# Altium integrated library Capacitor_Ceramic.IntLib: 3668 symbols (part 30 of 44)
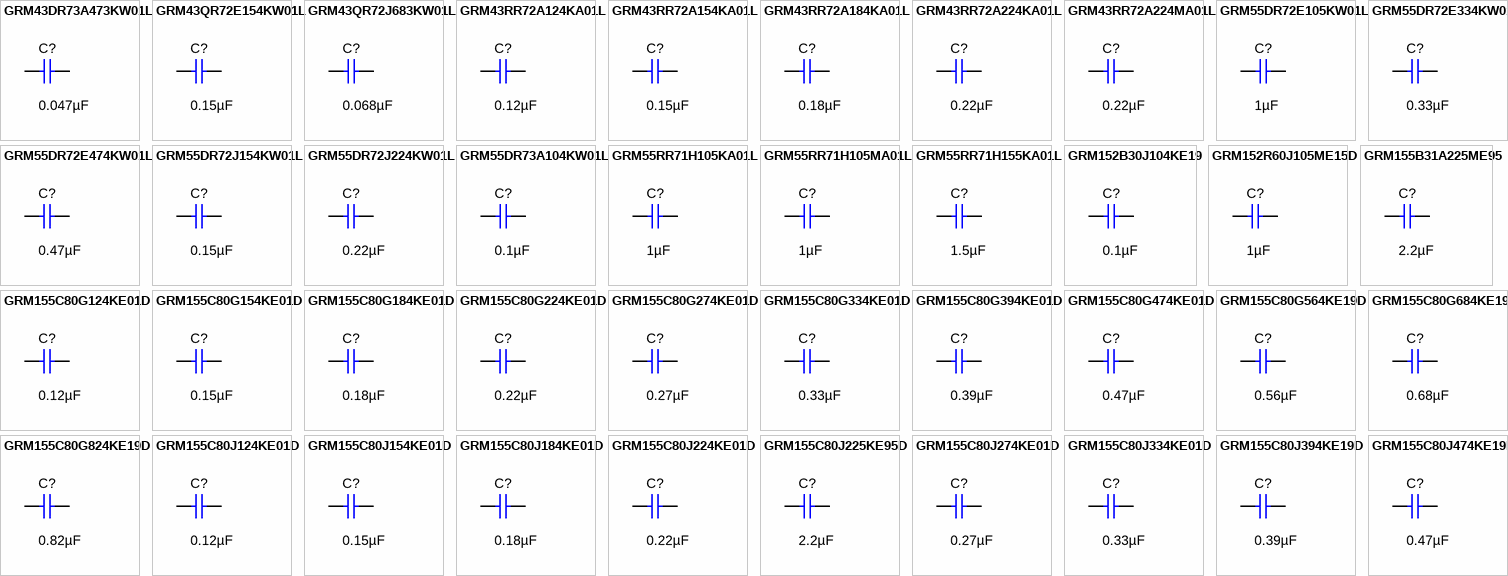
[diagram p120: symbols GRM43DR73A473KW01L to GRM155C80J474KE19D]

## GRM152R60J105ME15D
designator C?  ValueDisplayed: 1µF  (hidden comment: GRM152R60J105ME15D)
CAP, CERM, 1 µF, 6.3 V,+/- 20%, X5R, 0402; Manufacturer: MuRata; Polarized: N; CompType: Capacitor; Value: 1uF; U/M: EA; Cap_F: 0.000001; Tolerance_%: 20; VDC_V: 6.3; Value2: 6.3V; TaMin_C: -55; TaMax_C: 85; Cap_Case: 0402; SizeArea_mm2: 0.5; SizeAreaWB_mm2: 3; SizeX_mm: 1; SizeZ_mm: 0.6; AEC Category: Q200; Green_Lifecycle: Active; Green_REACh: Passed
signal-integrity model Cap
simulation model Cap
footprint 0402
footprint 0402M
footprint 0402L
footprint 0402S
pins: 1, 2

## GRM155B31A225ME95
designator C?  ValueDisplayed: 2.2µF  (hidden comment: GRM155B31A225ME95)
CAP, CERM, 2.2 µF, 10 V,+/- 20%, B, 0402; Manufacturer: MuRata; Polarized: N; CompType: Capacitor; Value: 2.2uF; U/M: EA; Cap_F: 0.0000022; Tolerance_%: 20; VDC_V: 10; Value2: 10V; TaMin_C: -25; TaMax_C: 85; Cap_Case: 0402; SizeArea_mm2: 0.5; SizeAreaWB_mm2: 3; SizeX_mm: 1; SizeZ_mm: 0.6; AEC Category: Q200
signal-integrity model Cap
simulation model Cap
footprint 0402
footprint 0402M
footprint 0402L
footprint 0402S
pins: 1, 2

## GRM155C80G124KE01D
designator C?  ValueDisplayed: 0.12µF  (hidden comment: GRM155C80G124KE01D)
CAP, CERM, 0.12 µF, 4 V,+/- 10%, X6S, 0402; Manufacturer: MuRata; Polarized: N; CompType: Capacitor; Value: 0.12uF; U/M: EA; Cap_F: 0.00000012; Tolerance_%: 10; VDC_V: 4; Value2: 4V; TaMin_C: -55; TaMax_C: 105; Cap_Case: 0402; SizeArea_mm2: 0.5; SizeAreaWB_mm2: 3; SizeX_mm: 1; SizeZ_mm: 0.6; AEC Category: Q200
signal-integrity model Cap
simulation model Cap
footprint 0402
footprint 0402M
footprint 0402L
footprint 0402S
pins: 1, 2

## GRM155C80G154KE01D
designator C?  ValueDisplayed: 0.15µF  (hidden comment: GRM155C80G154KE01D)
CAP, CERM, 0.15 µF, 4 V,+/- 10%, X6S, 0402; Manufacturer: MuRata; Polarized: N; CompType: Capacitor; Value: 0.15uF; U/M: EA; Cap_F: 0.00000015; Tolerance_%: 10; VDC_V: 4; Value2: 4V; TaMin_C: -55; TaMax_C: 105; Cap_Case: 0402; SizeArea_mm2: 0.5; SizeAreaWB_mm2: 3; SizeX_mm: 1; SizeZ_mm: 0.6; AEC Category: Q200
signal-integrity model Cap
simulation model Cap
footprint 0402
footprint 0402M
footprint 0402L
footprint 0402S
pins: 1, 2

## GRM155C80G184KE01D
designator C?  ValueDisplayed: 0.18µF  (hidden comment: GRM155C80G184KE01D)
CAP, CERM, 0.18 µF, 4 V,+/- 10%, X6S, 0402; Manufacturer: MuRata; Polarized: N; CompType: Capacitor; Value: 0.18uF; U/M: EA; Cap_F: 0.00000018; Tolerance_%: 10; VDC_V: 4; Value2: 4V; TaMin_C: -55; TaMax_C: 105; Cap_Case: 0402; SizeArea_mm2: 0.5; SizeAreaWB_mm2: 3; SizeX_mm: 1; SizeZ_mm: 0.6; AEC Category: Q200
signal-integrity model Cap
simulation model Cap
footprint 0402
footprint 0402M
footprint 0402L
footprint 0402S
pins: 1, 2

## GRM155C80G224KE01D
designator C?  ValueDisplayed: 0.22µF  (hidden comment: GRM155C80G224KE01D)
CAP, CERM, 0.22 µF, 4 V,+/- 10%, X6S, 0402; Manufacturer: MuRata; Polarized: N; CompType: Capacitor; Value: 0.22uF; U/M: EA; Cap_F: 0.00000022; Tolerance_%: 10; VDC_V: 4; Value2: 4V; TaMin_C: -55; TaMax_C: 105; Cap_Case: 0402; SizeArea_mm2: 0.5; SizeAreaWB_mm2: 3; SizeX_mm: 1; SizeZ_mm: 0.6; AEC Category: Q200
signal-integrity model Cap
simulation model Cap
footprint 0402
footprint 0402M
footprint 0402L
footprint 0402S
pins: 1, 2

## GRM155C80G274KE01D
designator C?  ValueDisplayed: 0.27µF  (hidden comment: GRM155C80G274KE01D)
CAP, CERM, 0.27 µF, 4 V,+/- 10%, X6S, 0402; Manufacturer: MuRata; Polarized: N; CompType: Capacitor; Value: 0.27uF; U/M: EA; Cap_F: 0.00000027; Tolerance_%: 10; VDC_V: 4; Value2: 4V; TaMin_C: -55; TaMax_C: 105; Cap_Case: 0402; SizeArea_mm2: 0.5; SizeAreaWB_mm2: 3; SizeX_mm: 1; SizeZ_mm: 0.6; AEC Category: Q200
signal-integrity model Cap
simulation model Cap
footprint 0402
footprint 0402M
footprint 0402L
footprint 0402S
pins: 1, 2

## GRM155C80G334KE01D
designator C?  ValueDisplayed: 0.33µF  (hidden comment: GRM155C80G334KE01D)
CAP, CERM, 0.33 µF, 4 V,+/- 10%, X6S, 0402; Manufacturer: MuRata; Polarized: N; CompType: Capacitor; Value: 0.33uF; U/M: EA; Cap_F: 0.00000033; Tolerance_%: 10; VDC_V: 4; Value2: 4V; TaMin_C: -55; TaMax_C: 105; Cap_Case: 0402; SizeArea_mm2: 0.5; SizeAreaWB_mm2: 3; SizeX_mm: 1; SizeZ_mm: 0.6; AEC Category: Q200
signal-integrity model Cap
simulation model Cap
footprint 0402
footprint 0402M
footprint 0402L
footprint 0402S
pins: 1, 2

## GRM155C80G394KE01D
designator C?  ValueDisplayed: 0.39µF  (hidden comment: GRM155C80G394KE01D)
CAP, CERM, 0.39 µF, 4 V,+/- 10%, X6S, 0402; Manufacturer: MuRata; Polarized: N; CompType: Capacitor; Value: 0.39uF; U/M: EA; Cap_F: 0.00000039; Tolerance_%: 10; VDC_V: 4; Value2: 4V; TaMin_C: -55; TaMax_C: 105; Cap_Case: 0402; SizeArea_mm2: 0.5; SizeAreaWB_mm2: 3; SizeX_mm: 1; SizeZ_mm: 0.6; AEC Category: Q200
signal-integrity model Cap
simulation model Cap
footprint 0402
footprint 0402M
footprint 0402L
footprint 0402S
pins: 1, 2

## GRM155C80G474KE01D
designator C?  ValueDisplayed: 0.47µF  (hidden comment: GRM155C80G474KE01D)
CAP, CERM, 0.47 µF, 4 V,+/- 10%, X6S, 0402; Manufacturer: MuRata; Polarized: N; CompType: Capacitor; Value: 0.47uF; U/M: EA; Cap_F: 0.00000047; Tolerance_%: 10; VDC_V: 4; Value2: 4V; TaMin_C: -55; TaMax_C: 105; Cap_Case: 0402; SizeArea_mm2: 0.5; SizeAreaWB_mm2: 3; SizeX_mm: 1; SizeZ_mm: 0.6; AEC Category: Q200
signal-integrity model Cap
simulation model Cap
footprint 0402
footprint 0402M
footprint 0402L
footprint 0402S
pins: 1, 2

## GRM155C80G564KE19D
designator C?  ValueDisplayed: 0.56µF  (hidden comment: GRM155C80G564KE19D)
CAP, CERM, 0.56 µF, 4 V,+/- 10%, X6S, 0402; Manufacturer: MuRata; Polarized: N; CompType: Capacitor; Value: 0.56uF; U/M: EA; Cap_F: 0.00000056; Tolerance_%: 10; VDC_V: 4; Value2: 4V; TaMin_C: -55; TaMax_C: 105; Cap_Case: 0402; SizeArea_mm2: 0.5; SizeAreaWB_mm2: 3; SizeX_mm: 1; SizeZ_mm: 0.6; AEC Category: Q200
signal-integrity model Cap
simulation model Cap
footprint 0402
footprint 0402M
footprint 0402L
footprint 0402S
pins: 1, 2

## GRM155C80G684KE19D
designator C?  ValueDisplayed: 0.68µF  (hidden comment: GRM155C80G684KE19D)
CAP, CERM, 0.68 µF, 4 V,+/- 10%, X6S, 0402; Manufacturer: MuRata; Polarized: N; CompType: Capacitor; Value: 0.68uF; U/M: EA; Cap_F: 0.00000068; Tolerance_%: 10; VDC_V: 4; Value2: 4V; TaMin_C: -55; TaMax_C: 105; Cap_Case: 0402; SizeArea_mm2: 0.5; SizeAreaWB_mm2: 3; SizeX_mm: 1; SizeZ_mm: 0.6; AEC Category: Q200
signal-integrity model Cap
simulation model Cap
footprint 0402
footprint 0402M
footprint 0402L
footprint 0402S
pins: 1, 2

## GRM155C80G824KE19D
designator C?  ValueDisplayed: 0.82µF  (hidden comment: GRM155C80G824KE19D)
CAP, CERM, 0.82 µF, 4 V,+/- 10%, X6S, 0402; Manufacturer: MuRata; Polarized: N; CompType: Capacitor; Value: 0.82uF; U/M: EA; Cap_F: 0.00000082; Tolerance_%: 10; VDC_V: 4; Value2: 4V; TaMin_C: -55; TaMax_C: 105; Cap_Case: 0402; SizeArea_mm2: 0.5; SizeAreaWB_mm2: 3; SizeX_mm: 1; SizeZ_mm: 0.6; AEC Category: Q200
signal-integrity model Cap
simulation model Cap
footprint 0402
footprint 0402M
footprint 0402L
footprint 0402S
pins: 1, 2

## GRM155C80J124KE01D
designator C?  ValueDisplayed: 0.12µF  (hidden comment: GRM155C80J124KE01D)
CAP, CERM, 0.12 µF, 6.3 V,+/- 10%, X6S, 0402; Manufacturer: MuRata; Polarized: N; CompType: Capacitor; Value: 0.12uF; U/M: EA; Cap_F: 0.00000012; Tolerance_%: 10; VDC_V: 6.3; Value2: 6.3V; TaMin_C: -55; TaMax_C: 105; Cap_Case: 0402; SizeArea_mm2: 0.5; SizeAreaWB_mm2: 3; SizeX_mm: 1; SizeZ_mm: 0.6; AEC Category: Q200
signal-integrity model Cap
simulation model Cap
footprint 0402
footprint 0402M
footprint 0402L
footprint 0402S
pins: 1, 2

## GRM155C80J154KE01D
designator C?  ValueDisplayed: 0.15µF  (hidden comment: GRM155C80J154KE01D)
CAP, CERM, 0.15 µF, 6.3 V,+/- 10%, X6S, 0402; Manufacturer: MuRata; Polarized: N; CompType: Capacitor; Value: 0.15uF; U/M: EA; Cap_F: 0.00000015; Tolerance_%: 10; VDC_V: 6.3; Value2: 6.3V; TaMin_C: -55; TaMax_C: 105; Cap_Case: 0402; SizeArea_mm2: 0.5; SizeAreaWB_mm2: 3; SizeX_mm: 1; SizeZ_mm: 0.6; AEC Category: Q200
signal-integrity model Cap
simulation model Cap
footprint 0402
footprint 0402M
footprint 0402L
footprint 0402S
pins: 1, 2

## GRM155C80J184KE01D
designator C?  ValueDisplayed: 0.18µF  (hidden comment: GRM155C80J184KE01D)
CAP, CERM, 0.18 µF, 6.3 V,+/- 10%, X6S, 0402; Manufacturer: MuRata; Polarized: N; CompType: Capacitor; Value: 0.18uF; U/M: EA; Cap_F: 0.00000018; Tolerance_%: 10; VDC_V: 6.3; Value2: 6.3V; TaMin_C: -55; TaMax_C: 105; Cap_Case: 0402; SizeArea_mm2: 0.5; SizeAreaWB_mm2: 3; SizeX_mm: 1; SizeZ_mm: 0.6; AEC Category: Q200
signal-integrity model Cap
simulation model Cap
footprint 0402
footprint 0402M
footprint 0402L
footprint 0402S
pins: 1, 2

## GRM155C80J224KE01D
designator C?  ValueDisplayed: 0.22µF  (hidden comment: GRM155C80J224KE01D)
CAP, CERM, 0.22 µF, 6.3 V,+/- 10%, X6S, 0402; Manufacturer: MuRata; Polarized: N; CompType: Capacitor; Value: 0.22uF; U/M: EA; Cap_F: 0.00000022; Tolerance_%: 10; VDC_V: 6.3; Value2: 6.3V; TaMin_C: -55; TaMax_C: 105; Cap_Case: 0402; SizeArea_mm2: 0.5; SizeAreaWB_mm2: 3; SizeX_mm: 1; SizeZ_mm: 0.6; AEC Category: Q200; Green_Lifecycle: Active; Green_REACh: Passed
signal-integrity model Cap
simulation model Cap
footprint 0402
footprint 0402M
footprint 0402L
footprint 0402S
pins: 1, 2

## GRM155C80J225KE95D
designator C?  ValueDisplayed: 2.2µF  (hidden comment: GRM155C80J225KE95D)
CAP, CERM, 2.2 µF, 6.3 V,+/- 10%, X6S, 0402; Manufacturer: MuRata; Polarized: N; CompType: Capacitor; Value: 2.2uF; U/M: EA; Cap_F: 0.0000022; Tolerance_%: 10; VDC_V: 6.3; Value2: 6.3V; TaMin_C: -55; TaMax_C: 105; Cap_Case: 0402; SizeArea_mm2: 0.5; SizeAreaWB_mm2: 3; SizeX_mm: 1; SizeZ_mm: 0.6; AEC Category: Q200; Green_Lifecycle: Active; Green_REACh: Passed
signal-integrity model Cap
simulation model Cap
footprint 0402
footprint 0402M
footprint 0402L
footprint 0402S
pins: 1, 2

## GRM155C80J274KE01D
designator C?  ValueDisplayed: 0.27µF  (hidden comment: GRM155C80J274KE01D)
CAP, CERM, 0.27 µF, 6.3 V,+/- 10%, X6S, 0402; Manufacturer: MuRata; Polarized: N; CompType: Capacitor; Value: 0.27uF; U/M: EA; Cap_F: 0.00000027; Tolerance_%: 10; VDC_V: 6.3; Value2: 6.3V; TaMin_C: -55; TaMax_C: 105; Cap_Case: 0402; SizeArea_mm2: 0.5; SizeAreaWB_mm2: 3; SizeX_mm: 1; SizeZ_mm: 0.6; AEC Category: Q200
signal-integrity model Cap
simulation model Cap
footprint 0402
footprint 0402M
footprint 0402L
footprint 0402S
pins: 1, 2

## GRM155C80J334KE01D
designator C?  ValueDisplayed: 0.33µF  (hidden comment: GRM155C80J334KE01D)
CAP, CERM, 0.33 µF, 6.3 V,+/- 10%, X6S, 0402; Manufacturer: MuRata; Polarized: N; CompType: Capacitor; Value: 0.33uF; U/M: EA; Cap_F: 0.00000033; Tolerance_%: 10; VDC_V: 6.3; Value2: 6.3V; TaMin_C: -55; TaMax_C: 105; Cap_Case: 0402; SizeArea_mm2: 0.5; SizeAreaWB_mm2: 3; SizeX_mm: 1; SizeZ_mm: 0.6; AEC Category: Q200; Green_Lifecycle: Active; Green_REACh: Passed
signal-integrity model Cap
simulation model Cap
footprint 0402
footprint 0402M
footprint 0402L
footprint 0402S
pins: 1, 2

## GRM155C80J394KE19D
designator C?  ValueDisplayed: 0.39µF  (hidden comment: GRM155C80J394KE19D)
CAP, CERM, 0.39 µF, 6.3 V,+/- 10%, X6S, 0402; Manufacturer: MuRata; Polarized: N; CompType: Capacitor; Value: 0.39uF; U/M: EA; Cap_F: 0.00000039; Tolerance_%: 10; VDC_V: 6.3; Value2: 6.3V; TaMin_C: -55; TaMax_C: 105; Cap_Case: 0402; SizeArea_mm2: 0.5; SizeAreaWB_mm2: 3; SizeX_mm: 1; SizeZ_mm: 0.6; AEC Category: Q200
signal-integrity model Cap
simulation model Cap
footprint 0402
footprint 0402M
footprint 0402L
footprint 0402S
pins: 1, 2

## GRM155C80J474KE19D
designator C?  ValueDisplayed: 0.47µF  (hidden comment: GRM155C80J474KE19D)
CAP, CERM, 0.47 µF, 6.3 V,+/- 10%, X6S, 0402; Manufacturer: MuRata; Polarized: N; CompType: Capacitor; Value: 0.47uF; U/M: EA; Cap_F: 0.00000047; Tolerance_%: 10; VDC_V: 6.3; Value2: 6.3V; TaMin_C: -55; TaMax_C: 105; Cap_Case: 0402; SizeArea_mm2: 0.5; SizeAreaWB_mm2: 3; SizeX_mm: 1; SizeZ_mm: 0.6; AEC Category: Q200
signal-integrity model Cap
simulation model Cap
footprint 0402
footprint 0402M
footprint 0402L
footprint 0402S
pins: 1, 2

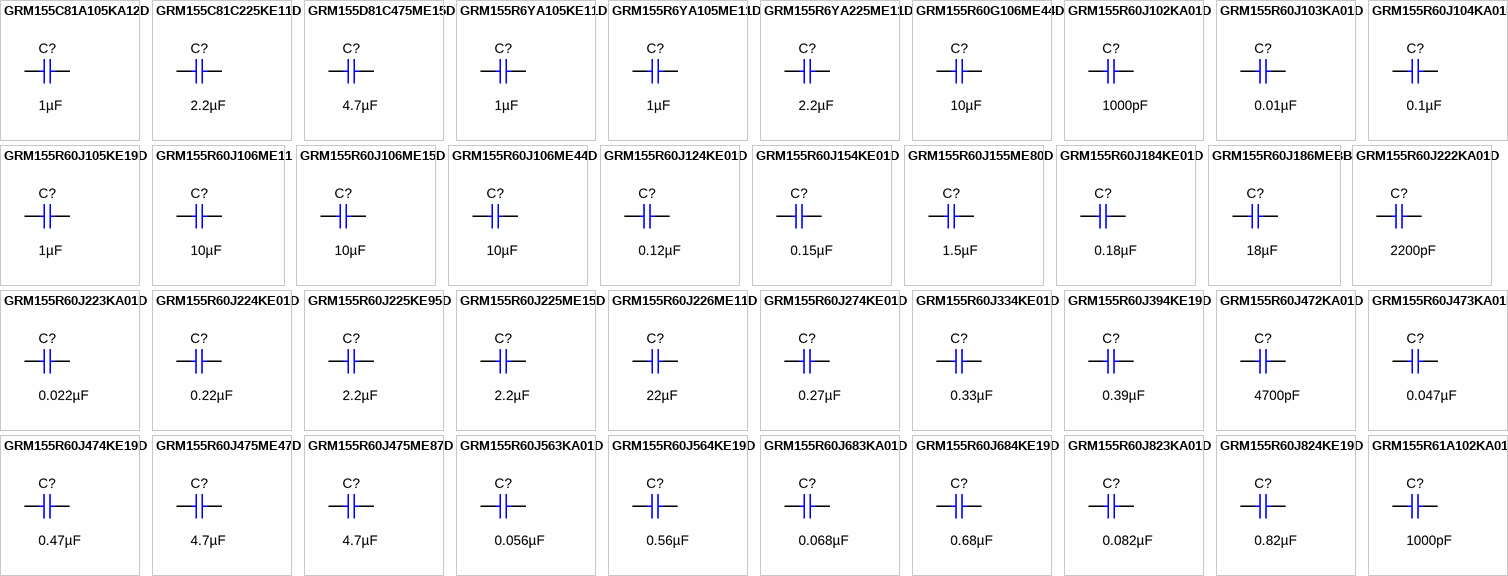
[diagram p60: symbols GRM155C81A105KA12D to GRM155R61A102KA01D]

## GRM155C81A105KA12D
designator C?  ValueDisplayed: 1µF  (hidden comment: GRM155C81A105KA12D)
CAP, CERM, 1 µF, 10 V,+/- 10%, X6S, 0402; Manufacturer: MuRata; Polarized: N; CompType: Capacitor; Value: 1uF; U/M: EA; Cap_F: 0.000001; Tolerance_%: 10; Value2: 10V; TaMin_C: -55; TaMax_C: 105; Cap_Case: 0402; SizeArea_mm2: 0.5; SizeAreaWB_mm2: 3; SizeX_mm: 1; SizeZ_mm: 0.6; AEC Category: Q200
signal-integrity model Cap
simulation model Cap
footprint 0402
footprint 0402M
footprint 0402L
footprint 0402S
pins: 1, 2

## GRM155C81C225KE11D
designator C?  ValueDisplayed: 2.2µF  (hidden comment: GRM155C81C225KE11D)
CAP, CERM, 2.2 µF, 16 V,+/- 10%, X6S, 0402; Manufacturer: MuRata; Polarized: N; CompType: Capacitor; Value: 2.2uF; U/M: EA; Cap_F: 0.0000022; Tolerance_%: 10; VDC_V: 16; Value2: 16V; TaMin_C: -55; TaMax_C: 105; Cap_Case: 0402; SizeArea_mm2: 0.5; SizeAreaWB_mm2: 3; SizeX_mm: 1; SizeZ_mm: 0.6; AEC Category: Q200
signal-integrity model Cap
simulation model Cap
footprint 0402
footprint 0402M
footprint 0402L
footprint 0402S
pins: 1, 2

## GRM155D81C475ME15D
designator C?  ValueDisplayed: 4.7µF  (hidden comment: GRM155D81C475ME15D)
CAP, CERM, 4.7 µF, 16 V,+/- 20%, X6T, 0402; Manufacturer: MuRata; Polarized: N; CompType: Capacitor; Value: 4.7uF; U/M: EA; Cap_F: 0.0000047; Tolerance_%: 20; VDC_V: 16; Value2: 16V; TaMin_C: -55; TaMax_C: 105; Cap_Case: 0402; SizeArea_mm2: 0.5; SizeAreaWB_mm2: 3; SizeX_mm: 1; SizeZ_mm: 0.7; AEC Category: Q200
signal-integrity model Cap
simulation model Cap
footprint 0402_070
pins: 1, 2

## GRM155R6YA105KE11D
designator C?  ValueDisplayed: 1µF  (hidden comment: GRM155R6YA105KE11D)
CAP, CERM, 1 µF, 35 V,+/- 10%, X5R, 0402; Manufacturer: MuRata; Polarized: N; CompType: Capacitor; Value: 1uF; U/M: EA; Cap_F: 0.000001; Tolerance_%: 10; VDC_V: 35; Value2: 35V; TaMin_C: -55; TaMax_C: 85; Cap_Case: 0402; SizeArea_mm2: 0.5; SizeAreaWB_mm2: 3; SizeX_mm: 1; SizeZ_mm: 0.6; AEC Category: Q200; Green_Lifecycle: Active; Green_REACh: Passed
signal-integrity model Cap
simulation model Cap
footprint 0402
footprint 0402M
footprint 0402L
footprint 0402S
pins: 1, 2

## GRM155R6YA105ME11D
designator C?  ValueDisplayed: 1µF  (hidden comment: GRM155R6YA105ME11D)
CAP, CERM, 1 µF, 35 V,+/- 20%, X5R, 0402; Manufacturer: MuRata; Polarized: N; CompType: Capacitor; Value: 1uF; U/M: EA; Cap_F: 0.000001; Tolerance_%: 20; VDC_V: 35; Value2: 35V; TaMin_C: -55; TaMax_C: 85; Cap_Case: 0402; SizeArea_mm2: 0.5; SizeAreaWB_mm2: 3; SizeX_mm: 1; SizeZ_mm: 0.6; AEC Category: Q200
signal-integrity model Cap
simulation model Cap
footprint 0402
footprint 0402M
footprint 0402L
footprint 0402S
pins: 1, 2

## GRM155R6YA225ME11D
designator C?  ValueDisplayed: 2.2µF  (hidden comment: GRM155R6YA225ME11D)
CAP, CERM, 2.2 µF, 35 V,+/- 20%, X5R, 0402; Manufacturer: MuRata; Polarized: N; CompType: Capacitor; Value: 2.2uF; U/M: EA; Cap_F: 0.0000022; Tolerance_%: 20; VDC_V: 35; Value2: 35V; TaMin_C: -55; TaMax_C: 85; Cap_Case: 0402; SizeArea_mm2: 0.5; SizeAreaWB_mm2: 3; SizeX_mm: 1; SizeZ_mm: 0.7; AEC Category: Q200
signal-integrity model Cap
simulation model Cap
footprint 0402_070
pins: 1, 2

## GRM155R60G106ME44D
designator C?  ValueDisplayed: 10µF  (hidden comment: GRM155R60G106ME44D)
CAP, CERM, 10 µF, 4 V,+/- 20%, X5R, 0402; Manufacturer: MuRata; Polarized: N; CompType: Capacitor; Value: 10uF; U/M: EA; Cap_F: 0.00001; Tolerance_%: 20; VDC_V: 4; Value2: 4V; TaMin_C: -55; TaMax_C: 85; Cap_Case: 0402; SizeArea_mm2: 0.5; SizeAreaWB_mm2: 3; SizeX_mm: 1; SizeZ_mm: 0.7; AEC Category: Q200; Green_Lifecycle: Active; Green_REACh: Passed
signal-integrity model Cap
simulation model Cap
footprint 0402_070
pins: 1, 2

## GRM155R60J102KA01D
designator C?  ValueDisplayed: 1000pF  (hidden comment: GRM155R60J102KA01D)
CAP, CERM, 1000 pF, 6.3 V,+/- 10%, X5R, 0402; Manufacturer: MuRata; Polarized: N; CompType: Capacitor; Value: 1000pF; U/M: EA; Cap_F: 0.000000001; Tolerance_%: 10; VDC_V: 6.3; Value2: 6.3V; TaMin_C: -55; TaMax_C: 85; Cap_Case: 0402; SizeArea_mm2: 0.5; SizeAreaWB_mm2: 3; SizeX_mm: 1; SizeZ_mm: 0.6; AEC Category: Q200; Green_Lifecycle: Active; Green_REACh: Passed
signal-integrity model Cap
simulation model Cap
footprint 0402
footprint 0402M
footprint 0402L
footprint 0402S
pins: 1, 2

## GRM155R60J103KA01D
designator C?  ValueDisplayed: 0.01µF  (hidden comment: GRM155R60J103KA01D)
CAP, CERM, 0.01 µF, 6.3 V,+/- 10%, X5R, 0402; Manufacturer: MuRata; Polarized: N; CompType: Capacitor; Value: 0.01uF; U/M: EA; Cap_F: 0.00000001; Tolerance_%: 10; VDC_V: 6.3; Value2: 6.3V; TaMin_C: -55; TaMax_C: 85; Cap_Case: 0402; SizeArea_mm2: 0.5; SizeAreaWB_mm2: 3; SizeX_mm: 1; SizeZ_mm: 0.6; AEC Category: Q200
signal-integrity model Cap
simulation model Cap
footprint 0402
footprint 0402M
footprint 0402L
footprint 0402S
pins: 1, 2

## GRM155R60J104KA01D
designator C?  ValueDisplayed: 0.1µF  (hidden comment: GRM155R60J104KA01D)
CAP, CERM, 0.1 µF, 6.3 V,+/- 10%, X5R, 0402; Manufacturer: MuRata; Polarized: N; CompType: Capacitor; Value: 0.1uF; U/M: EA; Cap_F: 0.0000001; Tolerance_%: 10; VDC_V: 6.3; Value2: 6.3V; TaMin_C: -55; TaMax_C: 85; Cap_Case: 0402; SizeArea_mm2: 0.5; SizeAreaWB_mm2: 3; SizeX_mm: 1; SizeZ_mm: 0.6; AEC Category: Q200; Green_Lifecycle: Active; Green_REACh: Passed
signal-integrity model Cap
simulation model Cap
footprint 0402
footprint 0402M
footprint 0402L
footprint 0402S
pins: 1, 2

## GRM155R60J105KE19D
designator C?  ValueDisplayed: 1µF  (hidden comment: GRM155R60J105KE19D)
CAP, CERM, 1 µF, 6.3 V,+/- 10%, X5R, 0402; Manufacturer: MuRata; Polarized: N; CompType: Capacitor; Value: 1uF; U/M: EA; Cap_F: 0.000001; Tolerance_%: 10; VDC_V: 6.3; Value2: 6.3V; TaMin_C: -55; TaMax_C: 85; Cap_Case: 0402; SizeArea_mm2: 0.5; SizeAreaWB_mm2: 3; SizeX_mm: 1; SizeZ_mm: 0.6; AEC Category: Q200; Green_Lifecycle: Active; Green_REACh: Passed
signal-integrity model Cap
simulation model Cap
footprint 0402
footprint 0402M
footprint 0402L
footprint 0402S
pins: 1, 2

## GRM155R60J106ME11
designator C?  ValueDisplayed: 10µF  (hidden comment: GRM155R60J106ME11)
CAP, CERM, 10 µF, 6.3 V,+/- 20%, X5R, 0402; Manufacturer: MuRata; Polarized: N; CompType: Capacitor; Value: 10uF; U/M: EA; Cap_F: 0.00001; Tolerance_%: 20; VDC_V: 6.3; Value2: 6.3V; TaMin_C: -55; TaMax_C: 85; Cap_Case: 0402; SizeArea_mm2: 0.5; SizeAreaWB_mm2: 3; SizeX_mm: 1; SizeZ_mm: 0.6; AEC Category: Q200; Green_Lifecycle: Not Set; Green_REACh: Incomplete
signal-integrity model Cap
simulation model Cap
footprint 0402
footprint 0402M
footprint 0402L
footprint 0402S
pins: 1, 2

## GRM155R60J106ME15D
designator C?  ValueDisplayed: 10µF  (hidden comment: GRM155R60J106ME15D)
CAP, CERM, 10 µF, 6.3 V,+/- 20%, X5R, 0402; Manufacturer: MuRata; Polarized: N; CompType: Capacitor; Value: 10uF; U/M: EA; Cap_F: 0.00001; Tolerance_%: 20; VDC_V: 6.3; Value2: 6.3V; TaMin_C: -55; TaMax_C: 85; Cap_Case: 0402; SizeArea_mm2: 0.5; SizeAreaWB_mm2: 3; SizeX_mm: 1; SizeZ_mm: 0.6; AEC Category: Q200; Green_Lifecycle: Active; Green_REACh: Passed
signal-integrity model Cap
simulation model Cap
footprint 0402
footprint 0402M
footprint 0402L
footprint 0402S
pins: 1, 2

## GRM155R60J106ME44D
designator C?  ValueDisplayed: 10µF  (hidden comment: GRM155R60J106ME44D)
CAP, CERM, 10 µF, 6.3 V,+/- 20%, X5R, 0402; Manufacturer: MuRata; Polarized: N; CompType: Capacitor; Value: 10uF; U/M: EA; Cap_F: 0.00001; Tolerance_%: 20; VDC_V: 6.3; Value2: 6.3V; TaMin_C: -55; TaMax_C: 85; Cap_Case: 0402; SizeArea_mm2: 0.5; SizeAreaWB_mm2: 3; SizeX_mm: 1; SizeZ_mm: 0.7; AEC Category: Q200; Green_Lifecycle: Not Set; Green_REACh: Incomplete
signal-integrity model Cap
simulation model Cap
footprint 0402_070
pins: 1, 2

## GRM155R60J124KE01D
designator C?  ValueDisplayed: 0.12µF  (hidden comment: GRM155R60J124KE01D)
CAP, CERM, 0.12 µF, 6.3 V,+/- 10%, X5R, 0402; Manufacturer: MuRata; Polarized: N; CompType: Capacitor; Value: 0.12uF; U/M: EA; Cap_F: 0.00000012; Tolerance_%: 10; VDC_V: 6.3; Value2: 6.3V; TaMin_C: -55; TaMax_C: 85; Cap_Case: 0402; SizeArea_mm2: 0.5; SizeAreaWB_mm2: 3; SizeX_mm: 1; SizeZ_mm: 0.6; AEC Category: Q200
signal-integrity model Cap
simulation model Cap
footprint 0402
footprint 0402M
footprint 0402L
footprint 0402S
pins: 1, 2

## GRM155R60J154KE01D
designator C?  ValueDisplayed: 0.15µF  (hidden comment: GRM155R60J154KE01D)
CAP, CERM, 0.15 µF, 6.3 V,+/- 10%, X5R, 0402; Manufacturer: MuRata; Polarized: N; CompType: Capacitor; Value: 0.15uF; U/M: EA; Cap_F: 0.00000015; Tolerance_%: 10; VDC_V: 6.3; Value2: 6.3V; TaMin_C: -55; TaMax_C: 85; Cap_Case: 0402; SizeArea_mm2: 0.5; SizeAreaWB_mm2: 3; SizeX_mm: 1; SizeZ_mm: 0.6; AEC Category: Q200
signal-integrity model Cap
simulation model Cap
footprint 0402
footprint 0402M
footprint 0402L
footprint 0402S
pins: 1, 2

## GRM155R60J155ME80D
designator C?  ValueDisplayed: 1.5µF  (hidden comment: GRM155R60J155ME80D)
CAP, CERM, 1.5 µF, 6.3 V,+/- 20%, X5R, 0402; Manufacturer: MuRata; Polarized: N; CompType: Capacitor; Value: 1.5uF; U/M: EA; Cap_F: 0.0000015; Tolerance_%: 20; VDC_V: 6.3; Value2: 6.3V; TaMin_C: -55; TaMax_C: 85; Cap_Case: 0402; SizeArea_mm2: 0.5; SizeAreaWB_mm2: 3; SizeX_mm: 1; SizeZ_mm: 0.6; AEC Category: Q200; Green_Lifecycle: Active; Green_REACh: Passed
signal-integrity model Cap
simulation model Cap
footprint 0402
footprint 0402M
footprint 0402L
footprint 0402S
pins: 1, 2

## GRM155R60J184KE01D
designator C?  ValueDisplayed: 0.18µF  (hidden comment: GRM155R60J184KE01D)
CAP, CERM, 0.18 µF, 6.3 V,+/- 10%, X5R, 0402; Manufacturer: MuRata; Polarized: N; CompType: Capacitor; Value: 0.18uF; U/M: EA; Cap_F: 0.00000018; Tolerance_%: 10; VDC_V: 6.3; Value2: 6.3V; TaMin_C: -55; TaMax_C: 85; Cap_Case: 0402; SizeArea_mm2: 0.5; SizeAreaWB_mm2: 3; SizeX_mm: 1; SizeZ_mm: 0.6; AEC Category: Q200
signal-integrity model Cap
simulation model Cap
footprint 0402
footprint 0402M
footprint 0402L
footprint 0402S
pins: 1, 2

## GRM155R60J186MEBB
designator C?  ValueDisplayed: 18µF  (hidden comment: GRM155R60J186MEBB)
CAP, CERM, 18 µF, 6.3 V,+/- 20%, X5R, 0402; Manufacturer: MuRata; Polarized: N; CompType: Capacitor; Value: 18uF; U/M: EA; Cap_F: 0.000018; Tolerance_%: 20; VDC_V: 6.3; Value2: 6.3V; TaMin_C: -55; TaMax_C: 85; Cap_Case: 0402; SizeArea_mm2: 0.5; SizeAreaWB_mm2: 3; SizeX_mm: 1; SizeZ_mm: 0.65; AEC Category: Q200
signal-integrity model Cap
simulation model Cap
footprint 0402_065
footprint 0402_065M
footprint 0402_065L
footprint 0402_065S
pins: 1, 2

## GRM155R60J222KA01D
designator C?  ValueDisplayed: 2200pF  (hidden comment: GRM155R60J222KA01D)
CAP, CERM, 2200 pF, 6.3 V,+/- 10%, X5R, 0402; Manufacturer: MuRata; Polarized: N; CompType: Capacitor; Value: 2200pF; U/M: EA; Cap_F: 0.0000000022; Tolerance_%: 10; VDC_V: 6.3; Value2: 6.3V; TaMin_C: -55; TaMax_C: 85; Cap_Case: 0402; SizeArea_mm2: 0.5; SizeAreaWB_mm2: 3; SizeX_mm: 1; SizeZ_mm: 0.6; AEC Category: Q200
signal-integrity model Cap
simulation model Cap
footprint 0402
footprint 0402M
footprint 0402L
footprint 0402S
pins: 1, 2

## GRM155R60J223KA01D
designator C?  ValueDisplayed: 0.022µF  (hidden comment: GRM155R60J223KA01D)
CAP, CERM, 0.022 µF, 6.3 V,+/- 10%, X5R, 0402; Manufacturer: MuRata; Polarized: N; CompType: Capacitor; Value: 0.022uF; U/M: EA; Cap_F: 0.000000022; Tolerance_%: 10; VDC_V: 6.3; Value2: 6.3V; TaMin_C: -55; TaMax_C: 85; Cap_Case: 0402; SizeArea_mm2: 0.5; SizeAreaWB_mm2: 3; SizeX_mm: 1; SizeZ_mm: 0.6; AEC Category: Q200
signal-integrity model Cap
simulation model Cap
footprint 0402
footprint 0402M
footprint 0402L
footprint 0402S
pins: 1, 2

## GRM155R60J224KE01D
designator C?  ValueDisplayed: 0.22µF  (hidden comment: GRM155R60J224KE01D)
CAP, CERM, 0.22 µF, 6.3 V,+/- 10%, X5R, 0402; Manufacturer: MuRata; Polarized: N; CompType: Capacitor; Value: 0.22uF; U/M: EA; Cap_F: 0.00000022; Tolerance_%: 10; VDC_V: 6.3; Value2: 6.3V; TaMin_C: -55; TaMax_C: 85; Cap_Case: 0402; SizeArea_mm2: 0.5; SizeAreaWB_mm2: 3; SizeX_mm: 1; SizeZ_mm: 0.6; AEC Category: Q200
signal-integrity model Cap
simulation model Cap
footprint 0402
footprint 0402M
footprint 0402L
footprint 0402S
pins: 1, 2

## GRM155R60J225KE95D
designator C?  ValueDisplayed: 2.2µF  (hidden comment: GRM155R60J225KE95D)
CAP, CERM, 2.2 µF, 6.3 V,+/- 10%, X5R, 0402; Manufacturer: MuRata; Polarized: N; CompType: Capacitor; Value: 2.2uF; U/M: EA; Cap_F: 0.0000022; Tolerance_%: 10; VDC_V: 6.3; Value2: 6.3V; TaMin_C: -55; TaMax_C: 85; Cap_Case: 0402; SizeArea_mm2: 0.5; SizeAreaWB_mm2: 3; SizeX_mm: 1; SizeZ_mm: 0.6; AEC Category: Q200
signal-integrity model Cap
simulation model Cap
footprint 0402
footprint 0402M
footprint 0402L
footprint 0402S
pins: 1, 2

## GRM155R60J225ME15D
designator C?  ValueDisplayed: 2.2µF  (hidden comment: GRM155R60J225ME15D)
CAP, CERM, 2.2 µF, 6.3 V,+/- 20%, X5R, 0402; Manufacturer: MuRata; Polarized: N; CompType: Capacitor; Value: 2.2uF; U/M: EA; Cap_F: 0.0000022; Tolerance_%: 20; ESR_ohm: 0.005; Value1: 0.005 ohm; VDC_V: 6.3; Value2: 6.3V; IRMS_A: 3.67; TaMin_C: -55; TaMax_C: 125; Cap_Case: 0402; SizeArea_mm2: 0.5; SizeAreaWB_mm2: 3; SizeX_mm: 1; SizeZ_mm: 0.6; AEC Category: Q200; Green_Lifecycle: Active; Green_REACh: Passed
signal-integrity model Cap
simulation model Cap
footprint 0402
footprint 0402M
footprint 0402L
footprint 0402S
pins: 1, 2

## GRM155R60J226ME11D
designator C?  ValueDisplayed: 22µF  (hidden comment: GRM155R60J226ME11D)
CAP, CERM, 22 µF, 6.3 V,+/- 20%, X5R, 0402; Manufacturer: MuRata; Polarized: N; CompType: Capacitor; Value: 22uF; U/M: EA; Cap_F: 0.000022; Tolerance_%: 20; VDC_V: 6.3; Value2: 6.3V; TaMin_C: -55; TaMax_C: 85; Cap_Case: 0402; SizeArea_mm2: 0.5; SizeAreaWB_mm2: 3; SizeX_mm: 1; SizeZ_mm: 0.6; AEC Category: Q200
signal-integrity model Cap
simulation model Cap
footprint 0402
footprint 0402M
footprint 0402L
footprint 0402S
pins: 1, 2

## GRM155R60J274KE01D
designator C?  ValueDisplayed: 0.27µF  (hidden comment: GRM155R60J274KE01D)
CAP, CERM, 0.27 µF, 6.3 V,+/- 10%, X5R, 0402; Manufacturer: MuRata; Polarized: N; CompType: Capacitor; Value: 0.27uF; U/M: EA; Cap_F: 0.00000027; Tolerance_%: 10; VDC_V: 6.3; Value2: 6.3V; TaMin_C: -55; TaMax_C: 85; Cap_Case: 0402; SizeArea_mm2: 0.5; SizeAreaWB_mm2: 3; SizeX_mm: 1; SizeZ_mm: 0.6; AEC Category: Q200
signal-integrity model Cap
simulation model Cap
footprint 0402
footprint 0402M
footprint 0402L
footprint 0402S
pins: 1, 2

## GRM155R60J334KE01D
designator C?  ValueDisplayed: 0.33µF  (hidden comment: GRM155R60J334KE01D)
CAP, CERM, 0.33 µF, 6.3 V,+/- 10%, X5R, 0402; Manufacturer: MuRata; Polarized: N; CompType: Capacitor; Value: 0.33uF; U/M: EA; Cap_F: 0.00000033; Tolerance_%: 10; VDC_V: 6.3; Value2: 6.3V; TaMin_C: -55; TaMax_C: 85; Cap_Case: 0402; SizeArea_mm2: 0.5; SizeAreaWB_mm2: 3; SizeX_mm: 1; SizeZ_mm: 0.6; AEC Category: Q200; Green_Lifecycle: Active; Green_REACh: Passed
signal-integrity model Cap
simulation model Cap
footprint 0402
footprint 0402M
footprint 0402L
footprint 0402S
pins: 1, 2

## GRM155R60J394KE19D
designator C?  ValueDisplayed: 0.39µF  (hidden comment: GRM155R60J394KE19D)
CAP, CERM, 0.39 µF, 6.3 V,+/- 10%, X5R, 0402; Manufacturer: MuRata; Polarized: N; CompType: Capacitor; Value: 0.39uF; U/M: EA; Cap_F: 0.00000039; Tolerance_%: 10; VDC_V: 6.3; Value2: 6.3V; TaMin_C: -55; TaMax_C: 85; Cap_Case: 0402; SizeArea_mm2: 0.5; SizeAreaWB_mm2: 3; SizeX_mm: 1; SizeZ_mm: 0.6; AEC Category: Q200
signal-integrity model Cap
simulation model Cap
footprint 0402
footprint 0402M
footprint 0402L
footprint 0402S
pins: 1, 2

## GRM155R60J472KA01D
designator C?  ValueDisplayed: 4700pF  (hidden comment: GRM155R60J472KA01D)
CAP, CERM, 4700 pF, 6.3 V,+/- 10%, X5R, 0402; Manufacturer: MuRata; Polarized: N; CompType: Capacitor; Value: 4700pF; U/M: EA; Cap_F: 0.0000000047; Tolerance_%: 10; VDC_V: 6.3; Value2: 6.3V; TaMin_C: -55; TaMax_C: 85; Cap_Case: 0402; SizeArea_mm2: 0.5; SizeAreaWB_mm2: 3; SizeX_mm: 1; SizeZ_mm: 0.6; AEC Category: Q200
signal-integrity model Cap
simulation model Cap
footprint 0402
footprint 0402M
footprint 0402L
footprint 0402S
pins: 1, 2

## GRM155R60J473KA01D
designator C?  ValueDisplayed: 0.047µF  (hidden comment: GRM155R60J473KA01D)
CAP, CERM, 0.047 µF, 6.3 V,+/- 10%, X5R, 0402; Manufacturer: MuRata; Polarized: N; CompType: Capacitor; Value: 0.047uF; U/M: EA; Cap_F: 0.000000047; Tolerance_%: 10; VDC_V: 6.3; Value2: 6.3V; TaMin_C: -55; TaMax_C: 85; Cap_Case: 0402; SizeArea_mm2: 0.5; SizeAreaWB_mm2: 3; SizeX_mm: 1; SizeZ_mm: 0.6; AEC Category: Q200; Green_Lifecycle: Active; Green_REACh: Passed
signal-integrity model Cap
simulation model Cap
footprint 0402
footprint 0402M
footprint 0402L
footprint 0402S
pins: 1, 2

## GRM155R60J474KE19D
designator C?  ValueDisplayed: 0.47µF  (hidden comment: GRM155R60J474KE19D)
CAP, CERM, 0.47 µF, 6.3 V,+/- 10%, X5R, 0402; Manufacturer: MuRata; Polarized: N; CompType: Capacitor; Value: 0.47uF; U/M: EA; Cap_F: 0.00000047; Tolerance_%: 10; VDC_V: 6.3; Value2: 6.3V; TaMin_C: -55; TaMax_C: 85; Cap_Case: 0402; SizeArea_mm2: 0.5; SizeAreaWB_mm2: 3; SizeX_mm: 1; SizeZ_mm: 0.6; AEC Category: Q200; Green_Lifecycle: Active; Green_REACh: Passed
signal-integrity model Cap
simulation model Cap
footprint 0402
footprint 0402M
footprint 0402L
footprint 0402S
pins: 1, 2

## GRM155R60J475ME47D
designator C?  ValueDisplayed: 4.7µF  (hidden comment: GRM155R60J475ME47D)
CAP, CERM, 4.7 µF, 6.3 V,+/- 20%, X5R, 0402; Manufacturer: MuRata; Polarized: N; CompType: Capacitor; Value: 4.7uF; U/M: EA; Cap_F: 0.0000047; Tolerance_%: 20; VDC_V: 6.3; Value2: 6.3V; TaMin_C: -55; TaMax_C: 85; Cap_Case: 0402; SizeArea_mm2: 0.5; SizeAreaWB_mm2: 3; SizeX_mm: 1; SizeZ_mm: 0.6; AEC Category: Q200; Green_Lifecycle: Active; Green_REACh: Passed
signal-integrity model Cap
simulation model Cap
footprint 0402
footprint 0402M
footprint 0402L
footprint 0402S
pins: 1, 2

## GRM155R60J475ME87D
designator C?  ValueDisplayed: 4.7µF  (hidden comment: GRM155R60J475ME87D)
CAP, CERM, 4.7 µF, 6.3 V,+/- 20%, X5R, 0402; Manufacturer: MuRata; Polarized: N; CompType: Capacitor; Value: 4.7uF; U/M: EA; Cap_F: 0.0000047; Tolerance_%: 20; ESR_ohm: 0.009; Value1: 0.009 ohm; VDC_V: 6.3; Value2: 6.3V; IRMS_A: 1.22; TaMin_C: -55; TaMax_C: 85; Cap_Case: 0402; SizeArea_mm2: 0.5; SizeAreaWB_mm2: 3; SizeX_mm: 1; SizeZ_mm: 0.6; AEC Category: Q200; Green_Lifecycle: Active; Green_REACh: Passed
signal-integrity model Cap
simulation model Cap
footprint 0402
footprint 0402M
footprint 0402L
footprint 0402S
pins: 1, 2

## GRM155R60J563KA01D
designator C?  ValueDisplayed: 0.056µF  (hidden comment: GRM155R60J563KA01D)
CAP, CERM, 0.056 µF, 6.3 V,+/- 10%, X5R, 0402; Manufacturer: MuRata; Polarized: N; CompType: Capacitor; Value: 0.056uF; U/M: EA; Cap_F: 0.000000056; Tolerance_%: 10; VDC_V: 6.3; Value2: 6.3V; TaMin_C: -55; TaMax_C: 85; Cap_Case: 0402; SizeArea_mm2: 0.5; SizeAreaWB_mm2: 3; SizeX_mm: 1; SizeZ_mm: 0.6; AEC Category: Q200
signal-integrity model Cap
simulation model Cap
footprint 0402
footprint 0402M
footprint 0402L
footprint 0402S
pins: 1, 2

## GRM155R60J564KE19D
designator C?  ValueDisplayed: 0.56µF  (hidden comment: GRM155R60J564KE19D)
CAP, CERM, 0.56 µF, 6.3 V,+/- 10%, X5R, 0402; Manufacturer: MuRata; Polarized: N; CompType: Capacitor; Value: 0.56uF; U/M: EA; Cap_F: 0.00000056; Tolerance_%: 10; VDC_V: 6.3; Value2: 6.3V; TaMin_C: -55; TaMax_C: 85; Cap_Case: 0402; SizeArea_mm2: 0.5; SizeAreaWB_mm2: 3; SizeX_mm: 1; SizeZ_mm: 0.6; AEC Category: Q200
signal-integrity model Cap
simulation model Cap
footprint 0402
footprint 0402M
footprint 0402L
footprint 0402S
pins: 1, 2

## GRM155R60J683KA01D
designator C?  ValueDisplayed: 0.068µF  (hidden comment: GRM155R60J683KA01D)
CAP, CERM, 0.068 µF, 6.3 V,+/- 10%, X5R, 0402; Manufacturer: MuRata; Polarized: N; CompType: Capacitor; Value: 0.068uF; U/M: EA; Cap_F: 0.000000068; Tolerance_%: 10; VDC_V: 6.3; Value2: 6.3V; TaMin_C: -55; TaMax_C: 85; Cap_Case: 0402; SizeArea_mm2: 0.5; SizeAreaWB_mm2: 3; SizeX_mm: 1; SizeZ_mm: 0.6; AEC Category: Q200
signal-integrity model Cap
simulation model Cap
footprint 0402
footprint 0402M
footprint 0402L
footprint 0402S
pins: 1, 2

## GRM155R60J684KE19D
designator C?  ValueDisplayed: 0.68µF  (hidden comment: GRM155R60J684KE19D)
CAP, CERM, 0.68 µF, 6.3 V,+/- 10%, X5R, 0402; Manufacturer: MuRata; Polarized: N; CompType: Capacitor; Value: 0.68uF; U/M: EA; Cap_F: 0.00000068; Tolerance_%: 10; VDC_V: 6.3; Value2: 6.3V; TaMin_C: -55; TaMax_C: 85; Cap_Case: 0402; SizeArea_mm2: 0.5; SizeAreaWB_mm2: 3; SizeX_mm: 1; SizeZ_mm: 0.6; AEC Category: Q200
signal-integrity model Cap
simulation model Cap
footprint 0402
footprint 0402M
footprint 0402L
footprint 0402S
pins: 1, 2

## GRM155R60J823KA01D
designator C?  ValueDisplayed: 0.082µF  (hidden comment: GRM155R60J823KA01D)
CAP, CERM, 0.082 µF, 6.3 V,+/- 10%, X5R, 0402; Manufacturer: MuRata; Polarized: N; CompType: Capacitor; Value: 0.082uF; U/M: EA; Cap_F: 0.000000082; Tolerance_%: 10; VDC_V: 6.3; Value2: 6.3V; TaMin_C: -55; TaMax_C: 85; Cap_Case: 0402; SizeArea_mm2: 0.5; SizeAreaWB_mm2: 3; SizeX_mm: 1; SizeZ_mm: 0.6; AEC Category: Q200
signal-integrity model Cap
simulation model Cap
footprint 0402
footprint 0402M
footprint 0402L
footprint 0402S
pins: 1, 2

## GRM155R60J824KE19D
designator C?  ValueDisplayed: 0.82µF  (hidden comment: GRM155R60J824KE19D)
CAP, CERM, 0.82 µF, 6.3 V,+/- 10%, X5R, 0402; Manufacturer: MuRata; Polarized: N; CompType: Capacitor; Value: 0.82uF; U/M: EA; Cap_F: 0.00000082; Tolerance_%: 10; VDC_V: 6.3; Value2: 6.3V; TaMin_C: -55; TaMax_C: 85; Cap_Case: 0402; SizeArea_mm2: 0.5; SizeAreaWB_mm2: 3; SizeX_mm: 1; SizeZ_mm: 0.6; AEC Category: Q200
signal-integrity model Cap
simulation model Cap
footprint 0402
footprint 0402M
footprint 0402L
footprint 0402S
pins: 1, 2

## GRM155R61A102KA01D
designator C?  ValueDisplayed: 1000pF  (hidden comment: GRM155R61A102KA01D)
CAP, CERM, 1000 pF, 10 V,+/- 10%, X5R, 0402; Manufacturer: MuRata; Polarized: N; CompType: Capacitor; Value: 1000pF; U/M: EA; Cap_F: 0.000000001; Tolerance_%: 10; Value2: 10V; TaMin_C: -55; TaMax_C: 85; Cap_Case: 0402; SizeArea_mm2: 0.5; SizeAreaWB_mm2: 3; SizeX_mm: 1; SizeZ_mm: 0.6; AEC Category: Q200; Green_Lifecycle: Active; Green_REACh: Passed
signal-integrity model Cap
simulation model Cap
footprint 0402
footprint 0402M
footprint 0402L
footprint 0402S
pins: 1, 2

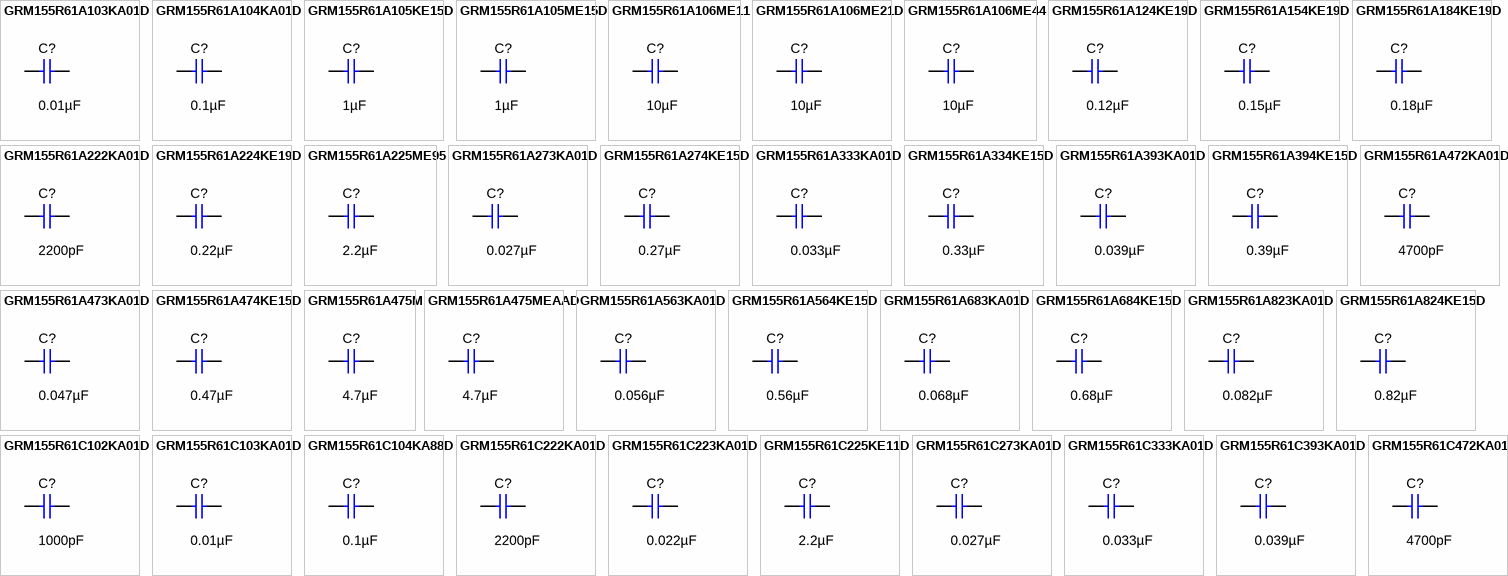
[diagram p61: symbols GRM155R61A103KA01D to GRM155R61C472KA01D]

## GRM155R61A103KA01D
designator C?  ValueDisplayed: 0.01µF  (hidden comment: GRM155R61A103KA01D)
CAP, CERM, 0.01 µF, 10 V,+/- 10%, X5R, 0402; Manufacturer: MuRata; Polarized: N; CompType: Capacitor; Value: 0.01uF; U/M: EA; Cap_F: 0.00000001; Tolerance_%: 10; Value2: 10V; TaMin_C: -55; TaMax_C: 85; Cap_Case: 0402; SizeArea_mm2: 0.5; SizeAreaWB_mm2: 3; SizeX_mm: 1; SizeZ_mm: 0.6; AEC Category: Q200; Green_Lifecycle: Active; Green_REACh: Passed
signal-integrity model Cap
simulation model Cap
footprint 0402
footprint 0402M
footprint 0402L
footprint 0402S
pins: 1, 2

## GRM155R61A104KA01D
designator C?  ValueDisplayed: 0.1µF  (hidden comment: GRM155R61A104KA01D)
CAP, CERM, 0.1 µF, 10 V,+/- 10%, X5R, 0402; Manufacturer: MuRata; Polarized: N; CompType: Capacitor; Value: 0.1uF; U/M: EA; Cap_F: 0.0000001; Tolerance_%: 10; Value2: 10V; TaMin_C: -55; TaMax_C: 85; Cap_Case: 0402; SizeArea_mm2: 0.5; SizeAreaWB_mm2: 3; SizeX_mm: 1; SizeZ_mm: 0.6; AEC Category: Q200; Green_Lifecycle: Active; Green_REACh: Passed
signal-integrity model Cap
simulation model Cap
footprint 0402
footprint 0402M
footprint 0402L
footprint 0402S
pins: 1, 2

## GRM155R61A105KE15D
designator C?  ValueDisplayed: 1µF  (hidden comment: GRM155R61A105KE15D)
CAP, CERM, 1 µF, 10 V,+/- 10%, X5R, 0402; Manufacturer: MuRata; Polarized: N; CompType: Capacitor; Value: 1uF; U/M: EA; Cap_F: 0.000001; Tolerance_%: 10; Value2: 10V; TaMin_C: -55; TaMax_C: 85; Cap_Case: 0402; SizeArea_mm2: 0.5; SizeAreaWB_mm2: 3; SizeX_mm: 1; SizeZ_mm: 0.6; AEC Category: Q200; Green_Lifecycle: Active; Green_REACh: Passed
signal-integrity model Cap
simulation model Cap
footprint 0402
footprint 0402M
footprint 0402L
footprint 0402S
pins: 1, 2

## GRM155R61A105ME15D
designator C?  ValueDisplayed: 1µF  (hidden comment: GRM155R61A105ME15D)
CAP, CERM, 1 µF, 10 V,+/- 20%, X5R, 0402; Manufacturer: MuRata; Polarized: N; CompType: Capacitor; Value: 1uF; U/M: EA; Cap_F: 0.000001; Tolerance_%: 20; VDC_V: 10; Value2: 10V; TaMin_C: -55; TaMax_C: 85; Cap_Case: 0402; SizeArea_mm2: 0.5; SizeAreaWB_mm2: 3; SizeX_mm: 1; SizeZ_mm: 0.6; AEC Category: Q200
signal-integrity model Cap
simulation model Cap
footprint 0402
footprint 0402M
footprint 0402L
footprint 0402S
pins: 1, 2

## GRM155R61A106ME11
designator C?  ValueDisplayed: 10µF  (hidden comment: GRM155R61A106ME11)
CAP, CERM, 10 µF, 10 V,+/- 20%, X5R, 0402; Manufacturer: MuRata; Polarized: N; CompType: Capacitor; Value: 10uF; U/M: EA; Cap_F: 0.00001; Tolerance_%: 20; VDC_V: 10; Value2: 10V; TaMin_C: -55; TaMax_C: 85; Cap_Case: 0402; SizeArea_mm2: 0.5; SizeAreaWB_mm2: 3; SizeX_mm: 1; SizeZ_mm: 0.6; AEC Category: Q200
signal-integrity model Cap
simulation model Cap
footprint 0402
footprint 0402M
footprint 0402L
footprint 0402S
pins: 1, 2

## GRM155R61A106ME21D
designator C?  ValueDisplayed: 10µF  (hidden comment: GRM155R61A106ME21D)
CAP, CERM, 10 µF, 10 V,+/- 20%, X5R, 0402; Manufacturer: MuRata; Polarized: N; CompType: Capacitor; Value: 10uF; U/M: EA; Cap_F: 0.00001; Tolerance_%: 20; VDC_V: 10; Value2: 10V; TaMin_C: -55; TaMax_C: 85; Cap_Case: 0402; SizeArea_mm2: 0.5; SizeAreaWB_mm2: 3; SizeX_mm: 1; SizeZ_mm: 0.7; AEC Category: Q200; Green_Lifecycle: Not Set; Green_REACh: Incomplete
signal-integrity model Cap
simulation model Cap
footprint 0402_070
pins: 1, 2

## GRM155R61A106ME44
designator C?  ValueDisplayed: 10µF  (hidden comment: GRM155R61A106ME44)
CAP, CERM, 10 µF, 10 V,+/- 20%, X5R, 0402; Manufacturer: MuRata; Polarized: N; CompType: Capacitor; Value: 10uF; U/M: EA; Cap_F: 0.00001; Tolerance_%: 20; VDC_V: 10; Value2: 10V; TaMin_C: -55; TaMax_C: 85; Cap_Case: 0402; SizeArea_mm2: 0.5; SizeAreaWB_mm2: 3; SizeX_mm: 1; SizeZ_mm: 0.7; AEC Category: Q200; Green_Lifecycle: Not Set; Green_REACh: Incomplete
signal-integrity model Cap
simulation model Cap
footprint 0402_070
pins: 1, 2

## GRM155R61A124KE19D
designator C?  ValueDisplayed: 0.12µF  (hidden comment: GRM155R61A124KE19D)
CAP, CERM, 0.12 µF, 10 V,+/- 10%, X5R, 0402; Manufacturer: MuRata; Polarized: N; CompType: Capacitor; Value: 0.12uF; U/M: EA; Cap_F: 0.00000012; Tolerance_%: 10; Value2: 10V; TaMin_C: -55; TaMax_C: 85; Cap_Case: 0402; SizeArea_mm2: 0.5; SizeAreaWB_mm2: 3; SizeX_mm: 1; SizeZ_mm: 0.6; AEC Category: Q200
signal-integrity model Cap
simulation model Cap
footprint 0402
footprint 0402M
footprint 0402L
footprint 0402S
pins: 1, 2

## GRM155R61A154KE19D
designator C?  ValueDisplayed: 0.15µF  (hidden comment: GRM155R61A154KE19D)
CAP, CERM, 0.15 µF, 10 V,+/- 10%, X5R, 0402; Manufacturer: MuRata; Polarized: N; CompType: Capacitor; Value: 0.15uF; U/M: EA; Cap_F: 0.00000015; Tolerance_%: 10; Value2: 10V; TaMin_C: -55; TaMax_C: 85; Cap_Case: 0402; SizeArea_mm2: 0.5; SizeAreaWB_mm2: 3; SizeX_mm: 1; SizeZ_mm: 0.6; AEC Category: Q200
signal-integrity model Cap
simulation model Cap
footprint 0402
footprint 0402M
footprint 0402L
footprint 0402S
pins: 1, 2

## GRM155R61A184KE19D
designator C?  ValueDisplayed: 0.18µF  (hidden comment: GRM155R61A184KE19D)
CAP, CERM, 0.18 µF, 10 V,+/- 10%, X5R, 0402; Manufacturer: MuRata; Polarized: N; CompType: Capacitor; Value: 0.18uF; U/M: EA; Cap_F: 0.00000018; Tolerance_%: 10; Value2: 10V; TaMin_C: -55; TaMax_C: 85; Cap_Case: 0402; SizeArea_mm2: 0.5; SizeAreaWB_mm2: 3; SizeX_mm: 1; SizeZ_mm: 0.6; AEC Category: Q200
signal-integrity model Cap
simulation model Cap
footprint 0402
footprint 0402M
footprint 0402L
footprint 0402S
pins: 1, 2

## GRM155R61A222KA01D
designator C?  ValueDisplayed: 2200pF  (hidden comment: GRM155R61A222KA01D)
CAP, CERM, 2200 pF, 10 V,+/- 10%, X5R, 0402; Manufacturer: MuRata; Polarized: N; CompType: Capacitor; Value: 2200pF; U/M: EA; Cap_F: 0.0000000022; Tolerance_%: 10; Value2: 10V; TaMin_C: -55; TaMax_C: 85; Cap_Case: 0402; SizeArea_mm2: 0.5; SizeAreaWB_mm2: 3; SizeX_mm: 1; SizeZ_mm: 0.6; AEC Category: Q200
signal-integrity model Cap
simulation model Cap
footprint 0402
footprint 0402M
footprint 0402L
footprint 0402S
pins: 1, 2

## GRM155R61A224KE19D
designator C?  ValueDisplayed: 0.22µF  (hidden comment: GRM155R61A224KE19D)
CAP, CERM, 0.22 µF, 10 V,+/- 10%, X5R, 0402; Manufacturer: MuRata; Polarized: N; CompType: Capacitor; Value: 0.22uF; U/M: EA; Cap_F: 0.00000022; Tolerance_%: 10; Value2: 10V; TaMin_C: -55; TaMax_C: 85; Cap_Case: 0402; SizeArea_mm2: 0.5; SizeAreaWB_mm2: 3; SizeX_mm: 1; SizeZ_mm: 0.6; AEC Category: Q200; Green_Lifecycle: Active; Green_REACh: Passed
signal-integrity model Cap
simulation model Cap
footprint 0402
footprint 0402M
footprint 0402L
footprint 0402S
pins: 1, 2

## GRM155R61A225ME95
designator C?  ValueDisplayed: 2.2µF  (hidden comment: GRM155R61A225ME95)
CAP, CERM, 2.2 µF, 10 V,+/- 20%, X5R, 0402; Manufacturer: MuRata; Polarized: N; CompType: Capacitor; Value: 2.2uF; U/M: EA; Cap_F: 0.0000022; Tolerance_%: 20; VDC_V: 10; Value2: 10V; TaMin_C: -55; TaMax_C: 85; Cap_Case: 0402; SizeArea_mm2: 0.5; SizeAreaWB_mm2: 3; SizeX_mm: 1; SizeZ_mm: 0.6; AEC Category: Q200
signal-integrity model Cap
simulation model Cap
footprint 0402
footprint 0402M
footprint 0402L
footprint 0402S
pins: 1, 2

## GRM155R61A273KA01D
designator C?  ValueDisplayed: 0.027µF  (hidden comment: GRM155R61A273KA01D)
CAP, CERM, 0.027 µF, 10 V,+/- 10%, X5R, 0402; Manufacturer: MuRata; Polarized: N; CompType: Capacitor; Value: 0.027uF; U/M: EA; Cap_F: 0.000000027; Tolerance_%: 10; Value2: 10V; TaMin_C: -55; TaMax_C: 85; Cap_Case: 0402; SizeArea_mm2: 0.5; SizeAreaWB_mm2: 3; SizeX_mm: 1; SizeZ_mm: 0.6; AEC Category: Q200
signal-integrity model Cap
simulation model Cap
footprint 0402
footprint 0402M
footprint 0402L
footprint 0402S
pins: 1, 2

## GRM155R61A274KE15D
designator C?  ValueDisplayed: 0.27µF  (hidden comment: GRM155R61A274KE15D)
CAP, CERM, 0.27 µF, 10 V,+/- 10%, X5R, 0402; Manufacturer: MuRata; Polarized: N; CompType: Capacitor; Value: 0.27uF; U/M: EA; Cap_F: 0.00000027; Tolerance_%: 10; Value2: 10V; TaMin_C: -55; TaMax_C: 85; Cap_Case: 0402; SizeArea_mm2: 0.5; SizeAreaWB_mm2: 3; SizeX_mm: 1; SizeZ_mm: 0.6; AEC Category: Q200; Green_Lifecycle: Active; Green_REACh: Passed
signal-integrity model Cap
simulation model Cap
footprint 0402
footprint 0402M
footprint 0402L
footprint 0402S
pins: 1, 2

## GRM155R61A333KA01D
designator C?  ValueDisplayed: 0.033µF  (hidden comment: GRM155R61A333KA01D)
CAP, CERM, 0.033 µF, 10 V,+/- 10%, X5R, 0402; Manufacturer: MuRata; Polarized: N; CompType: Capacitor; Value: 0.033uF; U/M: EA; Cap_F: 0.000000033; Tolerance_%: 10; Value2: 10V; TaMin_C: -55; TaMax_C: 85; Cap_Case: 0402; SizeArea_mm2: 0.5; SizeAreaWB_mm2: 3; SizeX_mm: 1; SizeZ_mm: 0.6; AEC Category: Q200; Green_Lifecycle: Active; Green_REACh: Passed
signal-integrity model Cap
simulation model Cap
footprint 0402
footprint 0402M
footprint 0402L
footprint 0402S
pins: 1, 2

## GRM155R61A334KE15D
designator C?  ValueDisplayed: 0.33µF  (hidden comment: GRM155R61A334KE15D)
CAP, CERM, 0.33 µF, 10 V,+/- 10%, X5R, 0402; Manufacturer: MuRata; Polarized: N; CompType: Capacitor; Value: 0.33uF; U/M: EA; Cap_F: 0.00000033; Tolerance_%: 10; Value2: 10V; TaMin_C: -55; TaMax_C: 85; Cap_Case: 0402; SizeArea_mm2: 0.5; SizeAreaWB_mm2: 3; SizeX_mm: 1; SizeZ_mm: 0.6; AEC Category: Q200
signal-integrity model Cap
simulation model Cap
footprint 0402
footprint 0402M
footprint 0402L
footprint 0402S
pins: 1, 2

## GRM155R61A393KA01D
designator C?  ValueDisplayed: 0.039µF  (hidden comment: GRM155R61A393KA01D)
CAP, CERM, 0.039 µF, 10 V,+/- 10%, X5R, 0402; Manufacturer: MuRata; Polarized: N; CompType: Capacitor; Value: 0.039uF; U/M: EA; Cap_F: 0.000000039; Tolerance_%: 10; Value2: 10V; TaMin_C: -55; TaMax_C: 85; Cap_Case: 0402; SizeArea_mm2: 0.5; SizeAreaWB_mm2: 3; SizeX_mm: 1; SizeZ_mm: 0.6; AEC Category: Q200
signal-integrity model Cap
simulation model Cap
footprint 0402
footprint 0402M
footprint 0402L
footprint 0402S
pins: 1, 2

## GRM155R61A394KE15D
designator C?  ValueDisplayed: 0.39µF  (hidden comment: GRM155R61A394KE15D)
CAP, CERM, 0.39 µF, 10 V,+/- 10%, X5R, 0402; Manufacturer: MuRata; Polarized: N; CompType: Capacitor; Value: 0.39uF; U/M: EA; Cap_F: 0.00000039; Tolerance_%: 10; Value2: 10V; TaMin_C: -55; TaMax_C: 85; Cap_Case: 0402; SizeArea_mm2: 0.5; SizeAreaWB_mm2: 3; SizeX_mm: 1; SizeZ_mm: 0.6; AEC Category: Q200
signal-integrity model Cap
simulation model Cap
footprint 0402
footprint 0402M
footprint 0402L
footprint 0402S
pins: 1, 2

## GRM155R61A472KA01D
designator C?  ValueDisplayed: 4700pF  (hidden comment: GRM155R61A472KA01D)
CAP, CERM, 4700 pF, 10 V,+/- 10%, X5R, 0402; Manufacturer: MuRata; Polarized: N; CompType: Capacitor; Value: 4700pF; U/M: EA; Cap_F: 0.0000000047; Tolerance_%: 10; Value2: 10V; TaMin_C: -55; TaMax_C: 85; Cap_Case: 0402; SizeArea_mm2: 0.5; SizeAreaWB_mm2: 3; SizeX_mm: 1; SizeZ_mm: 0.6; AEC Category: Q200
signal-integrity model Cap
simulation model Cap
footprint 0402
footprint 0402M
footprint 0402L
footprint 0402S
pins: 1, 2

## GRM155R61A473KA01D
designator C?  ValueDisplayed: 0.047µF  (hidden comment: GRM155R61A473KA01D)
CAP, CERM, 0.047 µF, 10 V,+/- 10%, X5R, 0402; Manufacturer: MuRata; Polarized: N; CompType: Capacitor; Value: 0.047uF; U/M: EA; Cap_F: 0.000000047; Tolerance_%: 10; Value2: 10V; TaMin_C: -55; TaMax_C: 85; Cap_Case: 0402; SizeArea_mm2: 0.5; SizeAreaWB_mm2: 3; SizeX_mm: 1; SizeZ_mm: 0.6; AEC Category: Q200
signal-integrity model Cap
simulation model Cap
footprint 0402
footprint 0402M
footprint 0402L
footprint 0402S
pins: 1, 2

## GRM155R61A474KE15D
designator C?  ValueDisplayed: 0.47µF  (hidden comment: GRM155R61A474KE15D)
CAP, CERM, 0.47 µF, 10 V,+/- 10%, X5R, 0402; Manufacturer: MuRata; Polarized: N; CompType: Capacitor; Value: 0.47uF; U/M: EA; Cap_F: 0.00000047; Tolerance_%: 10; Value2: 10V; TaMin_C: -55; TaMax_C: 85; Cap_Case: 0402; SizeArea_mm2: 0.5; SizeAreaWB_mm2: 3; SizeX_mm: 1; SizeZ_mm: 0.6; AEC Category: Q200; Green_Lifecycle: Active; Green_REACh: Passed
signal-integrity model Cap
simulation model Cap
footprint 0402
footprint 0402M
footprint 0402L
footprint 0402S
pins: 1, 2

## GRM155R61A475M
designator C?  ValueDisplayed: 4.7µF  (hidden comment: GRM155R61A475M)
CAP, CERM, 4.7 µF, 10 V,+/- 20%, X5R, 0402; Manufacturer: MuRata; Polarized: N; CompType: Capacitor; Value: 4.7uF; U/M: EA; Cap_F: 0.0000047; Tolerance_%: 20; VDC_V: 10; Value2: 10V; TaMin_C: -55; TaMax_C: 85; Cap_Case: 0402; SizeArea_mm2: 0.5; SizeAreaWB_mm2: 3; SizeX_mm: 1; SizeZ_mm: 0.6; AEC Category: Q200; Green_Lifecycle: Not Set; Green_REACh: Incomplete
signal-integrity model Cap
simulation model Cap
footprint 0402
footprint 0402M
footprint 0402L
footprint 0402S
pins: 1, 2

## GRM155R61A475MEAAD
designator C?  ValueDisplayed: 4.7µF  (hidden comment: GRM155R61A475MEAAD)
CAP, CERM, 4.7 µF, 10 V,+/- 20%, X5R, 0402; Manufacturer: MuRata; Polarized: N; CompType: Capacitor; Value: 4.7uF; U/M: EA; Cap_F: 0.0000047; Tolerance_%: 20; VDC_V: 10; Value2: 10V; TaMin_C: -55; TaMax_C: 85; Cap_Case: 0402; SizeArea_mm2: 0.5; SizeAreaWB_mm2: 3; SizeX_mm: 1; SizeZ_mm: 0.6; AEC Category: Q200; Green_Lifecycle: Active; Green_REACh: Passed
signal-integrity model Cap
simulation model Cap
footprint 0402
footprint 0402M
footprint 0402L
footprint 0402S
pins: 1, 2

## GRM155R61A563KA01D
designator C?  ValueDisplayed: 0.056µF  (hidden comment: GRM155R61A563KA01D)
CAP, CERM, 0.056 µF, 10 V,+/- 10%, X5R, 0402; Manufacturer: MuRata; Polarized: N; CompType: Capacitor; Value: 0.056uF; U/M: EA; Cap_F: 0.000000056; Tolerance_%: 10; Value2: 10V; TaMin_C: -55; TaMax_C: 85; Cap_Case: 0402; SizeArea_mm2: 0.5; SizeAreaWB_mm2: 3; SizeX_mm: 1; SizeZ_mm: 0.6; AEC Category: Q200; Green_Lifecycle: Active; Green_REACh: Passed
signal-integrity model Cap
simulation model Cap
footprint 0402
footprint 0402M
footprint 0402L
footprint 0402S
pins: 1, 2

## GRM155R61A564KE15D
designator C?  ValueDisplayed: 0.56µF  (hidden comment: GRM155R61A564KE15D)
CAP, CERM, 0.56 µF, 10 V,+/- 10%, X5R, 0402; Manufacturer: MuRata; Polarized: N; CompType: Capacitor; Value: 0.56uF; U/M: EA; Cap_F: 0.00000056; Tolerance_%: 10; Value2: 10V; TaMin_C: -55; TaMax_C: 85; Cap_Case: 0402; SizeArea_mm2: 0.5; SizeAreaWB_mm2: 3; SizeX_mm: 1; SizeZ_mm: 0.6; AEC Category: Q200
signal-integrity model Cap
simulation model Cap
footprint 0402
footprint 0402M
footprint 0402L
footprint 0402S
pins: 1, 2

## GRM155R61A683KA01D
designator C?  ValueDisplayed: 0.068µF  (hidden comment: GRM155R61A683KA01D)
CAP, CERM, 0.068 µF, 10 V,+/- 10%, X5R, 0402; Manufacturer: MuRata; Polarized: N; CompType: Capacitor; Value: 0.068uF; U/M: EA; Cap_F: 0.000000068; Tolerance_%: 10; Value2: 10V; TaMin_C: -55; TaMax_C: 85; Cap_Case: 0402; SizeArea_mm2: 0.5; SizeAreaWB_mm2: 3; SizeX_mm: 1; SizeZ_mm: 0.6; AEC Category: Q200
signal-integrity model Cap
simulation model Cap
footprint 0402
footprint 0402M
footprint 0402L
footprint 0402S
pins: 1, 2

## GRM155R61A684KE15D
designator C?  ValueDisplayed: 0.68µF  (hidden comment: GRM155R61A684KE15D)
CAP, CERM, 0.68 µF, 10 V,+/- 10%, X5R, 0402; Manufacturer: MuRata; Polarized: N; CompType: Capacitor; Value: 0.68uF; U/M: EA; Cap_F: 0.00000068; Tolerance_%: 10; Value2: 10V; TaMin_C: -55; TaMax_C: 85; Cap_Case: 0402; SizeArea_mm2: 0.5; SizeAreaWB_mm2: 3; SizeX_mm: 1; SizeZ_mm: 0.6; AEC Category: Q200
signal-integrity model Cap
simulation model Cap
footprint 0402
footprint 0402M
footprint 0402L
footprint 0402S
pins: 1, 2

## GRM155R61A823KA01D
designator C?  ValueDisplayed: 0.082µF  (hidden comment: GRM155R61A823KA01D)
CAP, CERM, 0.082 µF, 10 V,+/- 10%, X5R, 0402; Manufacturer: MuRata; Polarized: N; CompType: Capacitor; Value: 0.082uF; U/M: EA; Cap_F: 0.000000082; Tolerance_%: 10; Value2: 10V; TaMin_C: -55; TaMax_C: 85; Cap_Case: 0402; SizeArea_mm2: 0.5; SizeAreaWB_mm2: 3; SizeX_mm: 1; SizeZ_mm: 0.6; AEC Category: Q200
signal-integrity model Cap
simulation model Cap
footprint 0402
footprint 0402M
footprint 0402L
footprint 0402S
pins: 1, 2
